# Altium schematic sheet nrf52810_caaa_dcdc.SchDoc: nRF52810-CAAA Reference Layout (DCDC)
size A4; Revision: 1.0; SheetNumber: 1; SheetTotal: 1; DrawnBy: RUBR; DocumentSize: A4; PCAName: nRF52810-CAAA Reference Layout (DCDC)
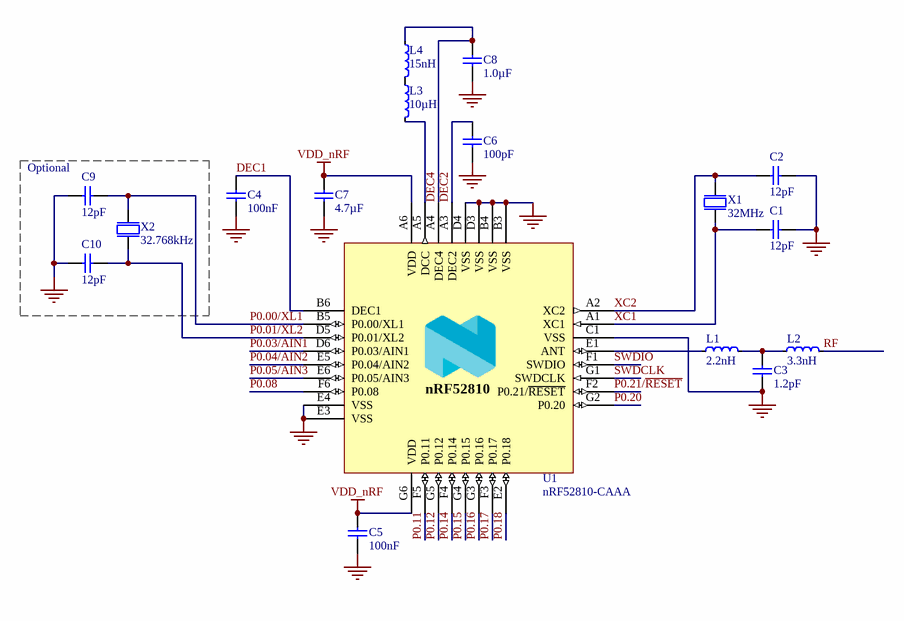
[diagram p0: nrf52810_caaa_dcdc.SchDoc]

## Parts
C1  12pF  [CAPC0603X03L_C]
C2  12pF  [CAPC0603X03L_C]
C3  1.2pF  [CAPC0603X03L_C]
C4  100nF  [CAPC0603X03L_C]
C5  100nF  [CAPC0603X03L_C]
C6  100pF  [CAPC0603X03L_C]
C7  4.7µF  [CAPC1608X06L]
C8  1.0µF  [CAPC1005X04L]
C9  12pF  [CAPC0603X03L_C]
C10  12pF  [CAPC0603X03L_C]
L1  2.2nH  [INDC0603X03L_C]
L2  3.3nH  [INDC0603X03L_C]
L3  10µH  [INDC1608X06L]
L4  15nH  [INDC1005X04L]
U1  nRF52810-CAAA  [BGA33C40P6X6_247X246X50]
X1  32MHz  [BT-XTAL_2016]
X2  32.768kHz  [XTAL_2012]

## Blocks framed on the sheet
Optional: C9 C10 X2

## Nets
GND: C1.1 C2.1 C3.1 C4.2 C5.2 C6.1 C7.2 C8.1 C9.1 C10.1 U1.B3(VSS) U1.B4(VSS) U1.C1(VSS) U1.D3(VSS) U1.D4(VSS) U1.E3(VSS) U1.E4(VSS) X1.2(GND) X1.4(GND)
VDD_nRF: C5.1 C7.1 U1.A6(VDD) U1.G6(VDD)
DEC1: C4.1 U1.B6(DEC1)
DEC2: C6.2 U1.A3(DEC2)
DEC4: C8.2 L4.1 U1.A4(DEC4)
P0.00/XL1: C9.2 U1.B5(P0.00/XL1) X2.1(inp)
P0.01/XL2: C10.2 U1.D5(P0.01/XL2) X2.2(out)
P0.03/AIN1: U1.D6(P0.03/AIN1)
P0.04/AIN2: U1.E5(P0.04/AIN2)
P0.05/AIN3: U1.E6(P0.05/AIN3)
P0.08: U1.F6(P0.08)
P0.11: U1.F5(P0.11)
P0.12: U1.G5(P0.12)
P0.14: U1.F4(P0.14)
P0.15: U1.G4(P0.15)
P0.16: U1.G3(P0.16)
P0.17: U1.F3(P0.17)
P0.18: U1.E2(P0.18)
P0.20: U1.G2(P0.20)
P0.21/~{RESET}: U1.F2(P0.21/~{RESET})
RF: L2.2
SWDCLK: U1.G1(SWDCLK)
SWDIO: U1.F1(SWDIO)
XC1: C1.2 U1.A1(XC1) X1.1(inp)
XC2: C2.2 U1.A2(XC2) X1.3(out)
NetC3_2: C3.2 L1.2 L2.1
NetL1_1: L1.1 U1.E1(ANT)
NetL3_1: L3.1 L4.2
NetL3_2: L3.2 U1.A5(DCC)

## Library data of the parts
C1 C2 C9 C10 = C0201-12p: Capacitor, NP0, ±2%
C3 = C0201-1.2p: Capacitor, NP0, ±5%
C4 C5 = C0201-100n: Capacitor, X5R, ±10%
C6 = C0201-100p: Capacitor, NP0, ±2%
C7 = C0603-4µ7: Capacitor, X5R, ±10%
C8 = C0402-1µ0: Capacitor, X5R, ±5%
L1 = L0201-2n2: High frequency chip inductor ±5%
L2 = L0201-3n3: High frequency chip inductor ±5%
L3 = L0603-10µ: Chip inductor, IDC,min = 50 mA, ±20%
L4 = L0402-15n: High frequency chip inductor ±10%
U1 = nRF52810-CAAA: Multi-protocol Bluetooth Low Energy, ANT and 2.4GHz proprietary system-on-chip; Manufacturer: Nordic Semiconductor
X1 = XTAL_SMD2016_32MHz_8pF_General: XTAL SMD 2016, 32MHz, Cl=8pF, Total Tol: ±40ppm
X2 = XTAL_SMD2012_32.768kHz_9pF_General: XTAL SMD 2012, 32.768kHz, Cl=9pF, Total Tol: ±50ppm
